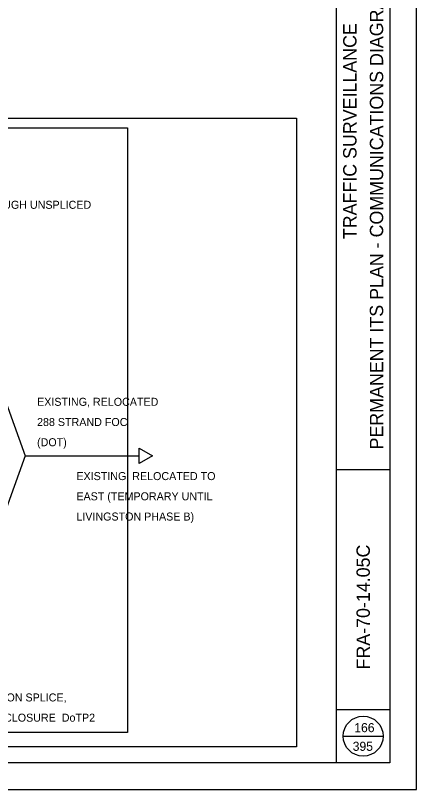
# Model space of a CAD drawing. Extents: x 1805893 to 1833564, y 708898 to 716199.
# Drawn here: x 1831852.1 to 1832002.5, y 714257.9 to 714548.1 of the extents above; entities that cross this region are included whole.
import ezdxf

# ---------------------------------------------------------------- set-up
doc = ezdxf.new("R2010")
doc.units = 0
for name, color, linetype in [('BR_P_Sub_Hidden', 7, 'Continuous'), ('SH_Border', 7, 'Continuous'), ('SH_Cut_Line', 7, 'Continuous'), ('SH_Data', 7, 'Continuous')]:
    doc.layers.add(name, color=color, linetype=linetype)

msp = doc.modelspace()

# ---------------------------------------------------------------- linework, layer by layer
at = {"layer": 'BR_P_Sub_Hidden'}
for points in [[(1831500.32, 714509.57), (1831957.51, 714509.57), (1831957.51, 714273.91), (1831500.32, 714273.91)], [(1831570.12, 714505.91), (1831894.14, 714505.91), (1831894.14, 714279.3), (1831570.12, 714279.3)]]:
    msp.add_lwpolyline(points, close=True, dxfattribs=at)
at = {"layer": 'SH_Border'}
for p, q in [((1831972.49, 714267.91), (1831972.49, 714687.91)), ((1831972.49, 714377.91), (1831992.49, 714377.91)), ((1831972.49, 714287.91), (1831992.49, 714287.91))]:
    msp.add_line(p, q, dxfattribs=at)
msp.add_lwpolyline([(1831362.49, 714687.91), (1831992.49, 714687.91), (1831992.49, 714267.91), (1831362.49, 714267.91)], close=True, dxfattribs=at)
at = {"layer": 'SH_Cut_Line'}
msp.add_lwpolyline([(1831322.49, 714257.91), (1832002.49, 714257.91), (1832002.49, 714697.91), (1831322.49, 714697.91)], close=True, dxfattribs=at)
at = {"layer": 'SH_Data'}
for p, q in [((1831898.54, 714380.09), (1831898.54, 714385.89)), ((1831898.54, 714385.89), (1831903.56, 714382.99)), ((1831855.81, 714382.99), (1831898.54, 714382.99)), ((1831903.56, 714382.99), (1831898.54, 714380.09)), ((1831974.99, 714277.91), (1831989.99, 714277.91))]:
    msp.add_line(p, q, dxfattribs=at)
msp.add_lwpolyline([(1831826.21, 714465.18), (1831855.81, 714382.99), (1831826.21, 714300.79)], dxfattribs=at)
msp.add_circle((1831982.49, 714277.91), 7.5, dxfattribs=at)

# ---------------------------------------------------------------- texts
for s, p in [('PERMANENT ITS PLAN - COMMUNICATIONS DIAGRAM - SE-DoTP2', (1831989.99, 714385.38)), ('TRAFFIC SURVEILLANCE', (1831979.99, 714464.23)), ('FRA-70-14.05C', (1831984.99, 714302.9))]:
    msp.add_text(s, height=5, rotation=90, dxfattribs=at).set_placement(p)
for s, height, p in [('0 BUFFER TUBES PASSED THROUGH UNSPLICED', 3, (1831783.78, 714475.62)), ('EXISTING, RELOCATED', 3, (1831860.23, 714401.76)), ('288 STRAND FOC', 3, (1831860.23, 714394.18)), ('(DOT)', 3, (1831860.23, 714386.6)), ('EXISTING, RELOCATED TO ', 3, (1831874.97, 714373.91)), ('EAST (TEMPORARY UNTIL ', 3, (1831874.97, 714366.33)), ('LIVINGSTON PHASE B)', 3, (1831874.97, 714358.75)), ('PROPOSED DOME, 800 FUSION SPLICE, ', 3, (1831793.7, 714290.93)), ('UNDERGROUND SPLICE ENCLOSURE  DoTP2', 3, (1831793.7, 714283.35)), ('166', 3.4, (1831979.16, 714279.41)), ('395', 3.4, (1831978.57, 714272.41))]:
    msp.add_text(s, height=height, dxfattribs=at).set_placement(p)

doc.saveas('drawing.dxf')
